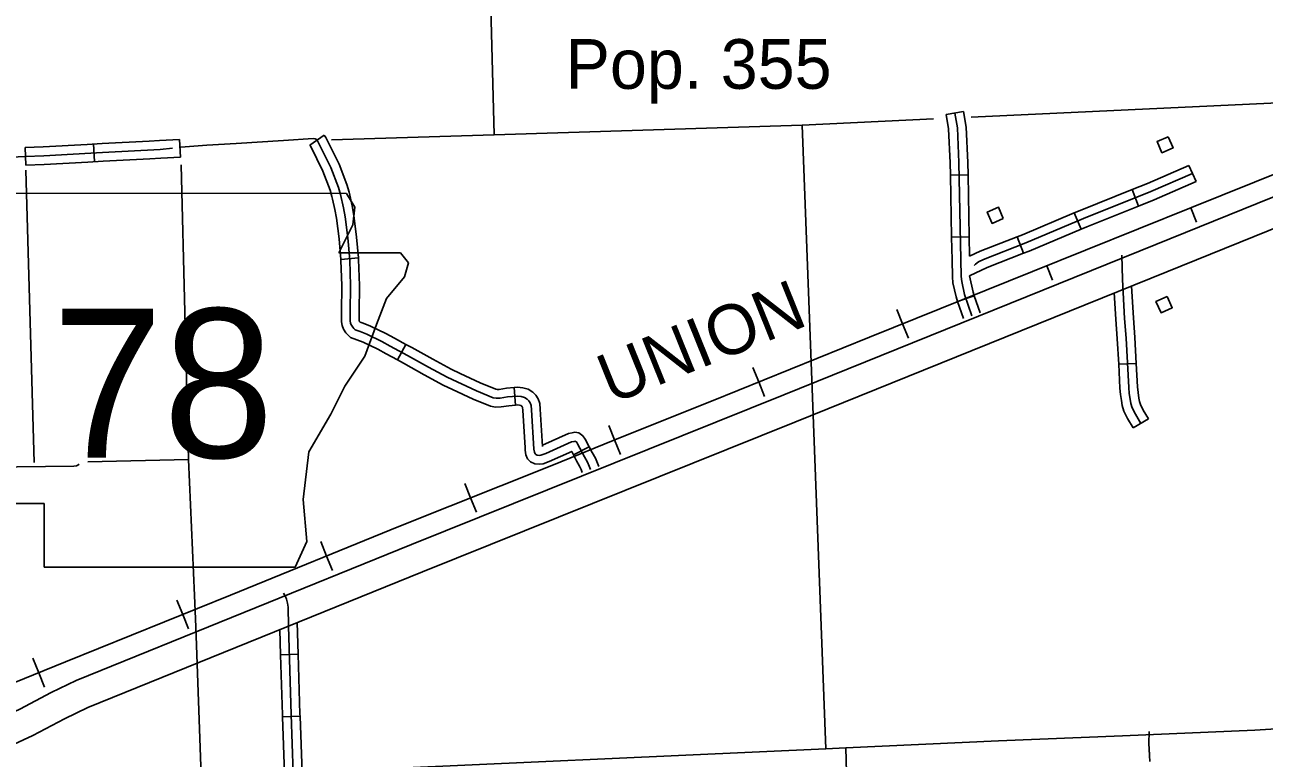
# Model space of a CAD drawing. Extents: x 1084508 to 1142749, y 1057638 to 1093403.
# Drawn here: x 1110633 to 1113940, y 1077671 to 1079628 of the extents above; entities that cross this region are included whole.
import ezdxf

# ---------------------------------------------------------------- set-up
doc = ezdxf.new("R2010")
doc.units = 0
for name, color, linetype in [('Level 15', 7, 'Continuous'), ('Level 2', 7, 'Continuous'), ('Level 21', 7, 'Continuous'), ('Level 32', 7, 'Continuous'), ('Level 34', 7, 'Continuous'), ('Level 40', 7, 'Continuous'), ('Level 43', 7, 'Continuous'), ('Level 45', 7, 'Continuous'), ('Level 5', 7, 'Continuous'), ('Level 56', 7, 'Continuous'), ('Level 6', 7, 'Continuous')]:
    doc.layers.add(name, color=color, linetype=linetype)

msp = doc.modelspace()

# ---------------------------------------------------------------- linework, layer by layer
at = {"layer": 'Level 15'}
for points in [[(1118020.1, 1080804.8), (1117454.8, 1080577.1), (1116519.3, 1080199.4), (1116394.7, 1080147.6), (1116308.1, 1080104.8), (1116151.2, 1080024.8), (1116076, 1079990.7), (1115983.7, 1079954.5), (1115857.6, 1079915.5), (1115726, 1079874.6), (1115624.4, 1079837.7), (1114621, 1079433.2), (1113651.5, 1079041.6), (1112659, 1078640), (1111665.4, 1078240.4), (1110770, 1077877.8), (1110703.6, 1077845.6), (1110619.8, 1077801.6), (1110387, 1077693.4)], [(1110420, 1077622.2), (1110654.6, 1077731.3), (1110738.9, 1077775.5), (1110801.9, 1077806.1), (1111694.8, 1078167.6), (1112688.3, 1078567.2), (1113680.9, 1078968.8), (1114650.4, 1079360.4), (1115652.5, 1079764.4), (1115751, 1079800.2), (1115880.8, 1079840.5), (1116009.6, 1079880.4), (1116106.5, 1079918.4), (1116185.3, 1079954.1), (1116343.3, 1080034.7), (1116427.2, 1080076.1), (1116549, 1080126.8), (1117484.2, 1080504.3), (1118049.4, 1080732)]]:
    msp.add_lwpolyline(points, dxfattribs=at)
at = {"layer": 'Level 2'}
msp.add_lwpolyline([(1111433.5, 1077634.8), (1112770.4, 1077695.6), (1112823.9, 1077698), (1113231.7, 1077716.6), (1113562.2, 1077730), (1113915.1, 1077745), (1114459.8, 1077779.5), (1116038.5, 1077854)], dxfattribs=at)
at = {"layer": 'Level 21'}
for p, q in [((1111491.7, 1079177.9), (1111513.8, 1079141.2)), ((1111513.8, 1079141.2), (1111508.5, 1079093.5)), ((1111508.5, 1079093.5), (1111471.3, 1079019.1)), ((1111471.3, 1079019.1), (1111635.9, 1079019.1)), ((1111635.9, 1079019.1), (1111657.1, 1078992.6)), ((1111657.1, 1078992.6), (1111646.5, 1078955.4)), ((1111646.5, 1078955.4), (1111598.7, 1078897)), ((1111598.7, 1078897), (1111572.2, 1078827.9)), ((1111572.2, 1078827.9), (1111540.3, 1078743)), ((1111540.3, 1078743), (1111487.2, 1078663.3)), ((1111487.2, 1078663.3), (1111450, 1078589)), ((1111450, 1078589), (1111391.6, 1078488.1)), ((1111391.6, 1078488.1), (1111375.7, 1078360.6)), ((1110685.4, 1078350), (1110605.7, 1078350)), ((1110685.4, 1078180.1), (1110685.4, 1078350)), ((1111375.7, 1078360.6), (1111386.3, 1078249.1)), ((1111386.3, 1078249.1), (1111354.5, 1078180.1)), ((1111354.5, 1078180.1), (1110685.4, 1078180.1))]:
    msp.add_line(p, q, dxfattribs=at)
msp.add_lwpolyline([(1110536.7, 1079178.4), (1111491.7, 1079177.9)], dxfattribs=at)
at = {"layer": 'Level 32'}
for p, q in [((1113091.6, 1079387.9), (1113137.9, 1079396.1)), ((1113103, 1079226.5), (1113150.1, 1079227.4)), ((1113739.6, 1079252.6), (1113758.5, 1079209.4)), ((1113587.9, 1079187.8), (1113605.4, 1079144.1)), ((1113433.8, 1079125.8), (1113452.1, 1079082.4)), ((1113106.3, 1079060.8), (1113153.3, 1079061.7)), ((1113281.5, 1079062), (1113298.6, 1079018.1)), ((1113122.4, 1078889.4), (1113166.9, 1078904.8)), ((1113599.1, 1078724.1), (1113552.1, 1078721.6)), ((1113631.3, 1078576), (1113590.7, 1078552.2)), ((1111315.9, 1077946.4), (1111363, 1077947.8)), ((1111320.8, 1077780.6), (1111367.8, 1077782.3))]:
    msp.add_line(p, q, dxfattribs=at)
for points in [[(1113114.7, 1079392), (1113121.7, 1079352.3), (1113125.9, 1079259.8), (1113131, 1079001.1), (1113131.9, 1078956.3), (1113133.3, 1078942.7), (1113140.8, 1078908.2), (1113160.4, 1078851.3)], [(1113137.9, 1079396.1), (1113145.2, 1079354.9), (1113149.5, 1079260.6), (1113150.1, 1079227.4)], [(1113091.6, 1079387.9), (1113098.3, 1079349.7), (1113102.4, 1079259.1), (1113103, 1079226.5)], [(1113103, 1079226.5), (1113106.3, 1079060.8)], [(1113150.1, 1079227.4), (1113153.3, 1079061.7)], [(1113749.1, 1079231), (1113638, 1079182.4), (1113458.3, 1079110.5), (1113304.2, 1079045.6), (1113191.7, 1079001.7), (1113178.2, 1078995.2), (1113169.8, 1078989.1), (1113166.7, 1078985.4)], [(1113739.6, 1079252.6), (1113628.9, 1079204.2), (1113587.9, 1079187.8)], [(1113758.5, 1079209.4), (1113647.1, 1079160.7), (1113605.4, 1079144.1)], [(1113587.9, 1079187.8), (1113449.3, 1079132.3), (1113433.8, 1079125.8)], [(1113433.8, 1079125.8), (1113295.4, 1079067.4), (1113281.5, 1079062)], [(1113605.4, 1079144.1), (1113467.2, 1079088.7), (1113452.1, 1079082.4)], [(1113106.3, 1079060.8), (1113107.4, 1079000.6), (1113108.4, 1078954.8), (1113110, 1078939), (1113118.1, 1078901.8), (1113122.4, 1078889.4)], [(1113153.3, 1079061.7), (1113154.4, 1079009.8)], [(1113281.5, 1079062), (1113182.3, 1079023.3), (1113154.4, 1079009.8)], [(1113452.1, 1079082.4), (1113313.1, 1079023.8), (1113298.6, 1079018.1)], [(1113298.6, 1079018.1), (1113201.1, 1078980.1), (1113154.2, 1078957.4)], [(1113611, 1078564.1), (1113596.7, 1078588.4), (1113588.1, 1078605.2), (1113584.4, 1078616.8), (1113582.6, 1078628.2), (1113580.5, 1078644), (1113578.9, 1078659.6), (1113572, 1078791.4), (1113567.8, 1078843.8), (1113562, 1078947.9), (1113560.2, 1079013.1)], [(1113154.2, 1078957.4), (1113163.5, 1078914.5), (1113166.9, 1078904.8)], [(1113599.1, 1078724.1), (1113595.5, 1078793), (1113591.3, 1078845.4), (1113586.5, 1078930.6)], [(1113166.9, 1078904.8), (1113182.7, 1078859)], [(1113552.1, 1078721.6), (1113548.5, 1078789.9), (1113544.3, 1078842.2), (1113540.4, 1078912)], [(1113122.4, 1078889.4), (1113138.1, 1078843.6)], [(1113590.7, 1078552.2), (1113576.1, 1078577.1), (1113566.3, 1078596.2), (1113561.5, 1078611.3), (1113559.3, 1078624.7), (1113557.1, 1078641.3), (1113555.4, 1078657.8), (1113552.1, 1078721.6)], [(1113631.3, 1078576), (1113617.4, 1078599.7), (1113610, 1078614.2), (1113607.4, 1078622.3), (1113605.9, 1078631.6), (1113603.9, 1078646.8), (1113602.4, 1078661.4), (1113599.1, 1078724.1)], [(1111324, 1078110.6), (1111328.8, 1078102.1), (1111331.4, 1078095.3), (1111334.1, 1078084.7), (1111335.7, 1078073.6), (1111337.2, 1078022.9), (1111344.1, 1077787.1), (1111349.8, 1077631)], [(1111314, 1078013.4), (1111315.9, 1077946.4)], [(1111360.5, 1078032.3), (1111363, 1077947.8)], [(1111315.9, 1077946.4), (1111320.6, 1077786.3), (1111320.8, 1077780.6)], [(1111363, 1077947.8), (1111367.6, 1077787.9), (1111367.8, 1077782.3)], [(1111320.8, 1077780.6), (1111326.3, 1077630.1)], [(1111367.8, 1077782.3), (1111373.3, 1077631.8)]]:
    msp.add_lwpolyline(points, dxfattribs=at)
at = {"layer": 'Level 34'}
for points in [[(1109796, 1079485.3), (1109799.3, 1079479.5), (1109802.5, 1079470.3), (1109803.2, 1079461.8), (1109805.8, 1079356.4), (1109807.9, 1079276.1), (1109807.9, 1079269.5), (1109808.6, 1079262.7), (1109810.9, 1079256.1), (1109814.1, 1079252.2), (1109820.4, 1079248.3), (1109826.2, 1079247), (1109834.8, 1079246.3), (1109856.3, 1079247), (1110024.8, 1079253.5), (1110212.8, 1079259.4), (1110366.2, 1079264.6), (1110458.1, 1079268.6), (1110635.1, 1079276.2)], [(1111049.5, 1079301.3), (1111119, 1079306.8), (1111197.5, 1079310.8), (1111323.9, 1079318.9), (1111402.4, 1079323.9), (1111408, 1079323.5), (1111412, 1079321.2), (1111413.1, 1079319.6)], [(1110384.3, 1078445.4), (1110764.1, 1078450), (1110771.3, 1078450.7), (1110775, 1078452.7), (1110778.4, 1078455.5)]]:
    msp.add_lwpolyline(points, dxfattribs=at)
at = {"layer": 'Level 40'}
for p, q in [((1113744.3, 1079139.5), (1113759.8, 1079101.1)), ((1113360.1, 1078984.3), (1113375.6, 1078945.9)), ((1112975.7, 1078829.8), (1112960.2, 1078868.2)), ((1112975.7, 1078829.8), (1112991.1, 1078791.3)), ((1112591.6, 1078674.6), (1112576, 1078713)), ((1112591.6, 1078674.6), (1112607.1, 1078636.2)), ((1112207.2, 1078519.8), (1112191.7, 1078558.3)), ((1112207.2, 1078519.8), (1112222.7, 1078481.4)), ((1111822.8, 1078365.2), (1111807.4, 1078403.6)), ((1111822.8, 1078365.2), (1111838.2, 1078326.7)), ((1111438.6, 1078210.1), (1111423, 1078248.5)), ((1111438.6, 1078210.1), (1111454.2, 1078171.7)), ((1111054.7, 1078054.2), (1111039.2, 1078092.6)), ((1111054.7, 1078054.2), (1111070.3, 1078015.8)), ((1110670.7, 1077898.7), (1110655.1, 1077937.1)), ((1110670.7, 1077898.7), (1110686.2, 1077860.3))]:
    msp.add_line(p, q, dxfattribs=at)
msp.add_lwpolyline([(1114164.2, 1079308.5), (1113746.2, 1079140.3), (1113322.1, 1078969), (1112887, 1078794.2), (1112466, 1078623.7), (1112227.5, 1078528), (1112039.2, 1078452), (1111631.7, 1078288.6), (1111182.3, 1078105.9), (1110742, 1077927.6), (1110351.1, 1077769.4), (1109917.3, 1077595), (1109521.2, 1077435.5), (1109497, 1077425.7)], dxfattribs=at)
msp.add_lwpolyline([(1114164.2, 1079308.5), (1113746.2, 1079140.3), (1113322.1, 1078969), (1112887, 1078794.2), (1112466, 1078623.7), (1112227.5, 1078528), (1112039.2, 1078452), (1111631.7, 1078288.6), (1111182.3, 1078105.9), (1110742, 1077927.6), (1110351.1, 1077769.4), (1109917.3, 1077595), (1109521.2, 1077435.5), (1109497, 1077425.7)], dxfattribs=at)
at = {"layer": 'Level 43'}
for points in [[(1113633.4, 1077742), (1113632.8, 1077709.8), (1113635.1, 1077661.9)], [(1113633.4, 1077742), (1113632.8, 1077709.8), (1113634.3, 1077679.9)]]:
    msp.add_lwpolyline(points, dxfattribs=at)
at = {"layer": 'Level 45'}
for p, q in [((1111393.8, 1079306.1), (1111432.4, 1079333.1)), ((1110636.1, 1079252.7), (1110634.1, 1079299.8)), ((1110819.3, 1079262.5), (1110816.9, 1079309.6)), ((1111048.5, 1079274.2), (1111046.1, 1079321.2)), ((1111476.5, 1079001.5), (1111523.4, 1079005.4)), ((1111627.6, 1078733.4), (1111649.9, 1078774.9)), ((1111942.9, 1078612.8), (1111938.8, 1078659.7)), ((1112097.4, 1078479.8), (1112139.1, 1078501.6))]:
    msp.add_line(p, q, dxfattribs=at)
for points in [[(1111432.4, 1079333.1), (1111436.9, 1079326.7), (1111471.8, 1079256), (1111492.5, 1079201.4), (1111498.6, 1079180.8), (1111500.4, 1079172.6)], [(1110634.1, 1079299.8), (1110682.6, 1079301.9), (1110799.3, 1079308.4)], [(1110635.1, 1079276.2), (1110683.8, 1079278.4), (1110840.8, 1079287.2), (1110994.9, 1079295.1), (1111027.8, 1079298.3)], [(1110799.3, 1079308.4), (1110839.6, 1079310.7), (1110964.9, 1079317.1)], [(1110964.9, 1079317.1), (1110993.1, 1079318.5), (1111046.1, 1079321.2)], [(1111393.8, 1079306.1), (1111396.2, 1079302.7), (1111428.6, 1079237.2), (1111447.8, 1079186.5), (1111452.9, 1079169.1), (1111454.4, 1079162.4)], [(1111413.1, 1079319.6), (1111416.5, 1079314.7), (1111450.2, 1079246.6), (1111470.2, 1079193.9), (1111475.7, 1079175), (1111483.6, 1079139.6), (1111488.2, 1079115.4), (1111495.4, 1079058.8), (1111500.3, 1078999.9), (1111502.8, 1078931.8), (1111501.5, 1078860.5), (1111501.8, 1078838.9), (1111502.8, 1078831), (1111504.8, 1078826.4), (1111508.4, 1078820.5), (1111511.3, 1078817.6), (1111514.9, 1078814), (1111528, 1078809.4), (1111546, 1078801.9), (1111585.9, 1078782.9), (1111608.5, 1078770.5), (1111654.7, 1078745.5), (1111710.3, 1078714.4), (1111760.1, 1078687.3), (1111838.9, 1078650.6), (1111883, 1078632.6), (1111891.5, 1078631), (1111901.7, 1078631.3), (1111921.6, 1078634.6), (1111948.1, 1078636.9), (1111957.6, 1078635.9), (1111966.8, 1078633.3), (1111974, 1078628.7), (1111978.2, 1078624.1), (1111981.8, 1078618.9), (1111984.1, 1078612), (1111985.4, 1078600.2), (1111992, 1078494.9), (1111993.3, 1078487), (1111994.9, 1078483.1), (1111997.2, 1078480.8), (1112000.8, 1078478.8), (1112005.4, 1078478.5), (1112010.6, 1078479.1), (1112024, 1078484.1), (1112092, 1078514.5), (1112098.9, 1078516.1), (1112100.9, 1078516.4), (1112102.8, 1078516.1), (1112105.1, 1078514.5), (1112108.4, 1078509.6), (1112126.4, 1078475.2), (1112134.9, 1078460.6), (1112139.5, 1078449.8), (1112142.7, 1078440.8)], [(1110636.1, 1079252.7), (1110685, 1079254.9), (1110801.9, 1079261.4)], [(1110801.9, 1079261.4), (1110842.1, 1079263.7), (1110967.3, 1079270.1)], [(1110967.3, 1079270.1), (1110996.6, 1079271.6), (1111048.5, 1079274.2)], [(1111454.4, 1079162.4), (1111460.5, 1079134.9), (1111464.9, 1079111.7), (1111472, 1079056.3), (1111476.5, 1079001.5)], [(1111500.4, 1079172.6), (1111506.7, 1079144.4), (1111511.4, 1079119.1), (1111518.8, 1079061.3), (1111523.4, 1079005.4)], [(1111476.5, 1079001.5), (1111476.8, 1078998.5), (1111479.3, 1078931.6), (1111478, 1078860.5), (1111478.3, 1078837.2), (1111478.6, 1078834.9)], [(1111523.4, 1079005.4), (1111523.8, 1079001.3), (1111526.4, 1078932), (1111525.1, 1078860.4), (1111525.4, 1078840.5), (1111525.3, 1078840.8)], [(1111478.6, 1078834.9), (1111479.9, 1078824.8), (1111483.8, 1078815.6), (1111489.8, 1078805.9), (1111494.7, 1078801), (1111502.1, 1078793.6), (1111519.6, 1078787.4), (1111536.4, 1078780.4), (1111575.2, 1078762), (1111597.2, 1078749.8), (1111627.6, 1078733.4)], [(1111525.3, 1078840.8), (1111525.8, 1078837.2), (1111527, 1078835.2), (1111527.8, 1078834.4), (1111536.4, 1078831.4), (1111555.6, 1078823.4), (1111596.6, 1078803.9), (1111619.7, 1078791.1), (1111649.9, 1078774.9)], [(1111649.9, 1078774.9), (1111666.1, 1078766.1), (1111721.7, 1078735), (1111770.7, 1078708.3), (1111794.6, 1078697.1)], [(1111627.6, 1078733.4), (1111643.4, 1078724.9), (1111699, 1078693.8), (1111749.4, 1078666.2), (1111774.8, 1078654.4)], [(1111794.6, 1078697.1), (1111848.3, 1078672.2), (1111889.8, 1078655.3), (1111893.4, 1078654.6), (1111899.4, 1078654.8), (1111918.7, 1078658), (1111938.8, 1078659.7)], [(1111774.8, 1078654.4), (1111829.5, 1078629), (1111876.3, 1078609.9), (1111889.7, 1078607.4), (1111904, 1078607.8), (1111924.6, 1078611.2), (1111942.9, 1078612.8)], [(1111938.8, 1078659.7), (1111948.3, 1078660.5), (1111962.1, 1078659.1), (1111976.5, 1078655), (1111989.2, 1078646.9), (1111996.6, 1078638.9), (1112003.1, 1078629.5), (1112007.2, 1078617.1), (1112008.9, 1078602.2), (1112015, 1078502.7)], [(1111942.9, 1078612.8), (1111947.9, 1078613.2), (1111953.1, 1078612.7), (1111957, 1078611.6), (1111958.8, 1078610.5), (1111959.8, 1078609.4), (1111960.5, 1078608.3), (1111961, 1078606.9), (1111961.9, 1078598.2), (1111968.1, 1078499.8)], [(1112014.9, 1078505.8), (1112015.1, 1078505.9), (1112084.4, 1078536.9), (1112094.2, 1078539.2), (1112100.9, 1078540.3), (1112112.1, 1078538.4), (1112122.3, 1078531.1), (1112128.7, 1078521.6), (1112139.1, 1078501.6)], [(1111968.1, 1078499.8), (1111968.5, 1078492.2), (1111970.5, 1078480.5), (1111975, 1078469.7), (1111982.9, 1078461.7), (1111994, 1078455.7), (1112006, 1078454.8), (1112016.2, 1078456.1), (1112032.9, 1078462.2), (1112092.6, 1078489), (1112097.4, 1078479.8)], [(1112139.1, 1078501.6), (1112147, 1078486.6), (1112156, 1078471.1), (1112161.4, 1078458.3), (1112164.8, 1078448.7)], [(1112097.4, 1078479.8), (1112105.8, 1078463.8), (1112113.8, 1078450), (1112117.5, 1078441.2), (1112120.5, 1078432.9)]]:
    msp.add_lwpolyline(points, dxfattribs=at)
at = {"layer": 'Level 5'}
for points in [[(1113158.1, 1079381.2), (1114320.1, 1079435.2)], [(1111885.8, 1079334.4), (1112708, 1079360.2)], [(1112708, 1079360.2), (1113058.2, 1079376.5)], [(1112708, 1079360.2), (1112770.4, 1077695.6)], [(1111050.7, 1079254.1), (1111069.9, 1078467.8)], [(1112823.9, 1077698), (1112852.8, 1076636.4)]]:
    msp.add_lwpolyline(points, dxfattribs=at)
at = {"layer": 'Level 56'}
for points in [[(1113684.5, 1079329.1), (1113697.5, 1079299.1), (1113667.4, 1079286.1), (1113654.4, 1079316)], [(1113244.3, 1079110.4), (1113214.2, 1079097.7), (1113201.5, 1079127.9), (1113231.6, 1079140.6)], [(1113681.4, 1078902.5), (1113694.9, 1078872.8), (1113665.1, 1078859.2), (1113651.6, 1078888.9)]]:
    msp.add_lwpolyline(points, close=True, dxfattribs=at)
at = {"layer": 'Level 6'}
for points in [[(1111868.8, 1079978.6), (1111885.8, 1079334.4), (1111451.7, 1079320.8)], [(1110636.2, 1079239.4), (1110658.7, 1078460)], [(1110801.1, 1078461.8), (1111070, 1078467.9), (1111086, 1078104.8), (1111089.7, 1078021.4), (1111104.2, 1077624.6), (1111128.5, 1077624.6)]]:
    msp.add_lwpolyline(points, dxfattribs=at)

# ---------------------------------------------------------------- texts
at = {"layer": 'Level 21'}
msp.add_text('78', height=397.75, dxfattribs=at).set_placement((1110706.4, 1078472.4))
at = {"layer": 'Level 40'}
msp.add_text('UNION', height=132.58, rotation=21.9742, dxfattribs=at).set_placement((1112197.5, 1078613.9))
at = {"layer": 'Level 6'}
msp.add_text('Pop. 355', height=132.58, dxfattribs=at).set_placement((1112076.3, 1079456.8))

doc.saveas('drawing.dxf')
